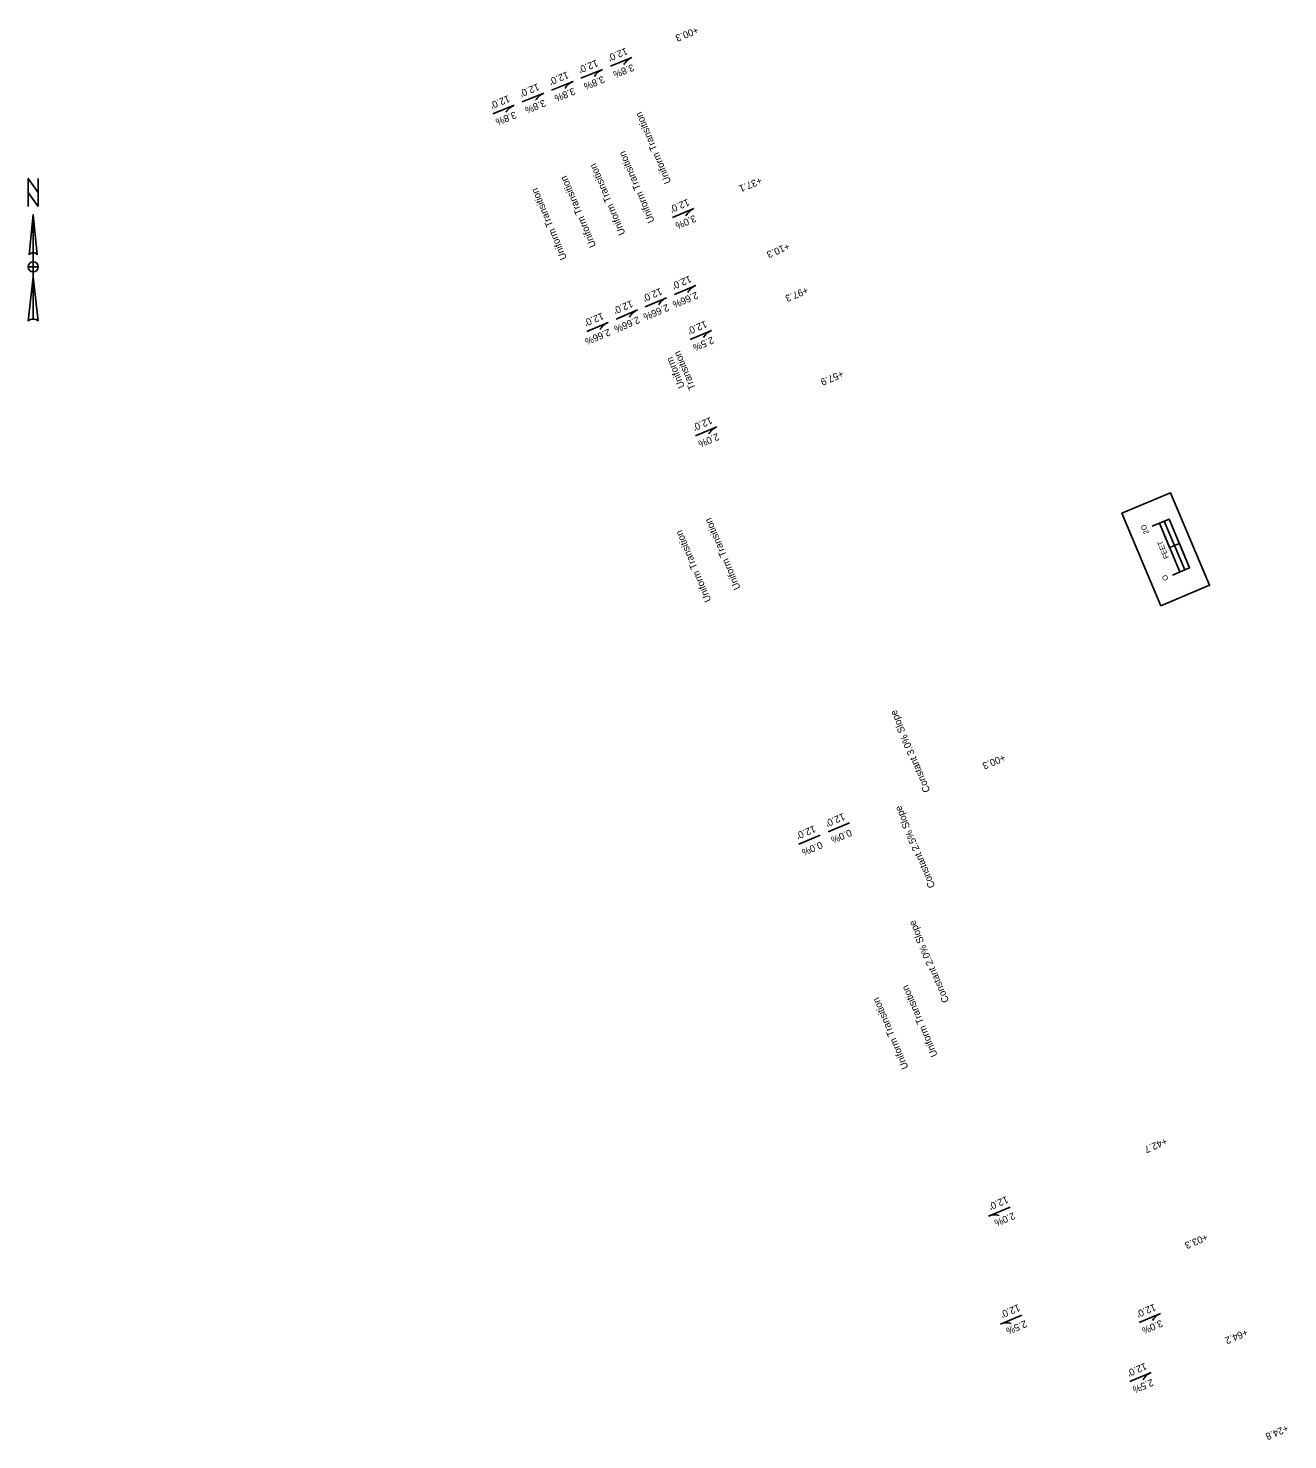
# Model space of a CAD drawing. Extents: x 20505303 to 20506906, y 7965397 to 7979025.
# Drawn here: x 20505734 to 20506210, y 7975973 to 7976507 of the extents above; entities that cross this region are included whole.
import ezdxf

# ---------------------------------------------------------------- set-up
doc = ezdxf.new("R2010")
doc.units = 0
doc.layers.add('_CIVIL_CONSTRUCTION', color=7, linetype='Continuous')
doc.layers.add('Alignment', color=7, linetype='Continuous')

msp = doc.modelspace()

# ---------------------------------------------------------------- linework, layer by layer
at = {"layer": '_CIVIL_CONSTRUCTION'}
for p, q in [((20505735.65, 7976436.36), (20505737.18, 7976421.15)), ((20505735.65, 7976436.36), (20505735.65, 7976396.81)), ((20505734.13, 7976421.15), (20505734.13, 7976421.15)), ((20505734.19, 7976421.29), (20505734.48, 7976421.6)), ((20505733.75, 7976396.04), (20505735.65, 7976412.78)), ((20505735.65, 7976414.68), (20505735.65, 7976414.68))]:
    msp.add_line(p, q, dxfattribs=at)
msp.add_lwpolyline([(20505737.56, 7976439.4), (20505733.75, 7976444.72), (20505733.75, 7976450.05), (20505737.56, 7976444.72)], close=True, dxfattribs=at)
for points in [[(20505733.75, 7976439.4), (20505733.75, 7976450.05), (20505737.56, 7976444.72), (20505737.56, 7976450.05)], [(20505734.13, 7976421.15), (20505735.65, 7976436.36), (20505735.65, 7976421.91)], [(20505735.65, 7976414.68), (20505735.65, 7976416.58), (20505733.75, 7976416.58)], [(20505737.56, 7976416.58), (20505735.65, 7976416.58), (20505735.65, 7976418.48)], [(20505735.65, 7976396.81), (20505735.65, 7976412.78), (20505737.56, 7976396.05)]]:
    msp.add_lwpolyline(points, dxfattribs=at)
for centre, radius, start, end in [((20505735.66, 7976420), 1.9, 90.0204, 143.1257), ((20505735.66, 7976420.01), 1.9, 36.8481, 90.0218), ((20505735.66, 7976416.58), 1.9, 90, 180), ((20505735.66, 7976416.58), 1.9, 180, 270), ((20505735.66, 7976416.58), 1.9, 0, 90), ((20505735.66, 7976416.58), 1.9, 270, 360), ((20505735.65, 7976394.05), 2.76, 89.9894, 133.619), ((20505735.66, 7976394.05), 2.76, 46.4021, 90.0006)]:
    msp.add_arc(centre, radius, start, end, dxfattribs=at)
at = {"layer": 'Alignment'}
for p, q in [((20505954.08, 7976492.47), (20505962.21, 7976495.75)), ((20505942.95, 7976487.98), (20505951.09, 7976491.26)), ((20505931.83, 7976483.49), (20505939.96, 7976486.77)), ((20505920.7, 7976479), (20505928.83, 7976482.28)), ((20505909.57, 7976474.51), (20505917.7, 7976477.79)), ((20505977.59, 7976435.21), (20505985.67, 7976438.62)), ((20505967.28, 7976401.5), (20505975.36, 7976404.91)), ((20505978.33, 7976406.17), (20505986.42, 7976409.58)), ((20505956.22, 7976396.84), (20505964.3, 7976400.25)), ((20505945.17, 7976392.17), (20505953.25, 7976395.58)), ((20505984.25, 7976389.12), (20505992.33, 7976392.53)), ((20505986.27, 7976352.64), (20505994.35, 7976356.05)), ((20506169.41, 7976311.89), (20506165.72, 7976310.34)), ((20506169.41, 7976311.89), (20506165.72, 7976310.34)), ((20506036.45, 7976202.76), (20506044.53, 7976206.17)), ((20506025.4, 7976198.1), (20506033.48, 7976201.51)), ((20506105.32, 7976060.76), (20506097.24, 7976057.35)), ((20506154.14, 7976017.08), (20506162.22, 7976020.49)), ((20506109.77, 7976019.88), (20506101.69, 7976016.47)), ((20506150.66, 7975994.71), (20506158.74, 7975998.12))]:
    msp.add_line(p, q, dxfattribs=at)
for points in [[(20506162.38, 7976288.33), (20506147.67, 7976323.36), (20506166.11, 7976331.11), (20506180.82, 7976296.07)], [(20506162.38, 7976288.33), (20506147.67, 7976323.36), (20506166.11, 7976331.11), (20506180.82, 7976296.07)], [(20506167.55, 7976311.11), (20506163.68, 7976320.33), (20506161.85, 7976319.56), (20506165.72, 7976310.34)], [(20506173.28, 7976302.67), (20506169.41, 7976311.89), (20506167.55, 7976311.11), (20506171.42, 7976301.89)]]:
    msp.add_lwpolyline(points, close=True, dxfattribs=at)
for points in [[(20506166.82, 7976299.96), (20506173.28, 7976302.67), (20506165.54, 7976321.11), (20506159.08, 7976318.4)], [(20506169.59, 7976301.12), (20506161.85, 7976319.56)]]:
    msp.add_lwpolyline(points, dxfattribs=at)
for centre, start, end in [((20505964.52, 7976490.04), 111.9773, 150.1803), ((20505953.39, 7976485.55), 111.9773, 150.1803), ((20505942.27, 7976481.05), 111.9773, 150.1803), ((20505931.14, 7976476.56), 111.9773, 150.1803), ((20505920.01, 7976472.07), 111.9773, 150.1803), ((20505988.07, 7976432.94), 112.8763, 151.0793), ((20505977.76, 7976399.23), 112.8763, 151.0793), ((20505988.81, 7976403.9), 112.8763, 151.0793), ((20505966.7, 7976394.57), 112.8763, 151.0793), ((20505955.64, 7976389.9), 112.8763, 151.0793), ((20505994.73, 7976386.85), 112.8763, 151.0793), ((20505996.74, 7976350.37), 112.8763, 151.0793), ((20506099.63, 7976051.67), 74.6732, 112.8763), ((20506164.61, 7976014.81), 112.8763, 151.0793), ((20506104.08, 7976010.79), 74.6732, 112.8763), ((20506161.14, 7975992.44), 112.8763, 151.0793)]:
    msp.add_arc(centre, 6.16, start, end, dxfattribs=at)

# ---------------------------------------------------------------- texts
for s, height, rotation, p in [('+00.3', 2.664, 201.9773, (20505986.78, 7976507.54)), ("12.0'", 2.664, 202.08, (20505959.92, 7976499.57)), ("12.0'", 2.664, 202.08, (20505937.66, 7976490.58)), ("12.0'", 2.664, 202.08, (20505948.79, 7976495.07)), ('3.8%', 2.664, 202.08, (20505962.4, 7976493.42)), ("12.0'", 2.664, 202.08, (20505926.54, 7976486.09)), ('3.8%', 2.664, 202.08, (20505951.27, 7976488.93)), ("12.0'", 2.664, 202.08, (20505915.41, 7976481.6)), ('3.8%', 2.664, 202.08, (20505929.01, 7976479.95)), ('3.8%', 2.664, 202.08, (20505940.14, 7976484.44)), ('3.8%', 2.664, 202.08, (20505917.89, 7976475.46)), ('Uniform Transition', 2.664, 112.8763, (20505977.12, 7976448.68)), ('Uniform Transition', 2.664, 112.8763, (20505970.86, 7976433.85)), ('Uniform Transition', 2.664, 112.8763, (20505959.8, 7976429.19)), ('Uniform Transition', 2.664, 112.8763, (20505948.75, 7976424.52)), ('+37.1', 2.664, 202.8779, (20506010.78, 7976450.66)), ('Uniform Transition', 2.664, 112.8763, (20505937.69, 7976419.86)), ("12.0'", 2.664, 202.979, (20505983.32, 7976442.4)), ('3.0%', 2.664, 202.979, (20505985.89, 7976436.29)), ('+10.3', 2.664, 202.8779, (20506021.28, 7976425.73)), ("12.0'", 2.664, 202.979, (20505984.06, 7976413.35)), ("12.0'", 2.664, 202.979, (20505973.01, 7976408.69)), ('2.66%', 2.664, 202.979, (20505986.63, 7976407.25)), ('+97.3', 2.664, 202.8779, (20506028.28, 7976409.14)), ("12.0'", 2.664, 202.979, (20505961.95, 7976404.02)), ('2.66%', 2.664, 202.979, (20505975.58, 7976402.59)), ("12.0'", 2.664, 202.979, (20505950.89, 7976399.36)), ('2.66%', 2.664, 202.979, (20505964.52, 7976397.92)), ("12.0'", 2.664, 202.979, (20505989.98, 7976396.3)), ('2.66%', 2.664, 202.979, (20505953.47, 7976393.26)), ('2.5%', 2.664, 202.979, (20505992.55, 7976390.2)), ('Transition', 2.664, 112.8763, (20505986.43, 7976370.63)), ('Uniform', 2.664, 112.8763, (20505982.32, 7976371.27)), ('+57.9', 2.664, 202.8779, (20506041.67, 7976377.47)), ("12.0'", 2.664, 202.979, (20505991.99, 7976359.83)), ('2.0%', 2.664, 202.979, (20505994.57, 7976353.72)), ('Uniform Transition', 2.664, 112.8763, (20506003.39, 7976295.02)), ('Uniform Transition', 2.664, 112.8763, (20505992.33, 7976290.36)), ('2O', 2, 112.7764, (20506157.96, 7976315.89)), ('FEET', 2, 112.7764, (20506165.55, 7976306.59)), ('O', 2, 112.7764, (20506165.36, 7976298.27)), ('Constant 3.0% Slope', 2.664, 112.7854, (20506075.19, 7976218.32)), ('+00.3', 2.664, 202.8779, (20506102.92, 7976232.25)), ('Constant 2.5% Slope', 2.664, 112.8763, (20506077.05, 7976182.13)), ("12.0'", 2.664, 202.979, (20506042.18, 7976209.95)), ("12.0'", 2.664, 202.979, (20506031.12, 7976205.28)), ('0.0%', 2.664, 202.979, (20506044.75, 7976203.84)), ('0.0%', 2.664, 202.979, (20506033.7, 7976199.18)), ('Constant 2.0% Slope', 2.664, 112.8763, (20506082.33, 7976138.74)), ('Uniform Transition', 2.664, 112.8763, (20506077.98, 7976118.23)), ('Uniform Transition', 2.664, 112.8763, (20506066.92, 7976113.56)), ('+42.7', 2.664, 202.8779, (20506164.19, 7976087.05)), ("12.0'", 2.664, 202.979, (20506104, 7976064.98)), ('2.0%', 2.664, 202.979, (20506106.58, 7976058.88)), ('+03.3', 2.664, 202.8779, (20506179.5, 7976050.75)), ("12.0'", 2.664, 202.979, (20506108.46, 7976024.1)), ("12.0'", 2.664, 202.979, (20506159.86, 7976024.26)), ('2.5%', 2.664, 202.979, (20506111.03, 7976017.99)), ('3.0%', 2.664, 202.979, (20506162.44, 7976018.16)), ('+64.2', 2.664, 202.8779, (20506194.69, 7976014.74)), ("12.0'", 2.664, 202.979, (20506156.39, 7976001.9)), ('2.5%', 2.664, 202.979, (20506158.96, 7975995.8)), ('+24.8', 2.664, 202.8779, (20506210.05, 7975978.45))]:
    msp.add_text(s, height=height, rotation=rotation, dxfattribs=at).set_placement(p)

doc.saveas('drawing.dxf')
